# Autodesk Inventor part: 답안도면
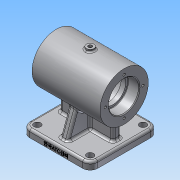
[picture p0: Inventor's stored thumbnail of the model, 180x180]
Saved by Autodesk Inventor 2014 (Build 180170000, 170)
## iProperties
Created: 2019-06
Part Number: 답안도면
Material: 알루미늄 6061
Document SubType Name: Modeling
Designer: NET
Density: 2.71 g/cm^3
Appearance: 알루미늄 - 평지
Mass: 642.889 g
Surface Area: 616.801 cm^2
Volume: 237.228 cm^3
Author: NET
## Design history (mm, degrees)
sketch "스케치1"
  geometry: L1 (45, 0)-(-45, 0); L2 (45, 0)-(45, 32); L3 (45, 32)-(-45, 32); L4 (-45, 32)-(-45, 0); L5 (45, 20)-(30.6, 20); L6 (30, 19.4)-(30, 17); L7 (30, 17)-(24, 17); L8 (24, 17)-(24, 22); L9 (21, 25)-(-21, 25); L10 (-24, 22)-(-24, 17); L11 (-24, 17)-(-30, 17); L12 (-30, 17)-(-30, 19.4); L13 (-30.6, 20)-(-45, 20); A1 r 3 centre (21, 22) between (24, 22) and (21, 25); A2 r 3 centre (-21, 22) between (-21, 25) and (-24, 22); A3 r 0.6 centre (30.6, 19.4) between (30.6, 20) and (30, 19.4); A4 r 0.6 centre (-30.6, 19.4) between (-30, 19.4) and (-30.6, 20); 7 further points
  constraints: 26 end point, 10 point on line, 8 point on circle, 8 tangent, 7 parallel, 5 perpendicular, 4 centre point, 2 equal radius, 2 midpoint, 1 coincident, 1 horizontal, 1 vertical alignment
  dimensions: "d0" = 90 distance of L1.start L1.end; "d1" = 64 diameter of L3 L1; "d2" = 40 diameter of L5 L1; "d3" = 34 diameter of L7 L1; "d4" = 50 diameter of L9 L1; "d5" = 40 diameter of L13 L1; "d6" = 34 diameter of L11 L1; "d7" = 48 distance of point (24, 25) point (-24, 25); "d8" = 15 distance of point (-30, 20) L13.end; "d9" = 15 distance of L5.start point (30, 20); "d10" = 3 radius of A1; "d11" = 0.6 radius of A3
revolve "회전1" sketch "스케치1" stored, may be unused: angle "d12" = 90 deg
chamfer "모따기1" distance "d13" = 1; stored, may be unused: second distance "d14" = 2, angle "d15" = 45 deg
sketch "스케치2"
  geometry: C1 r 32 at (0, 0) reference; 1 further point
  constraints: 1 vertical alignment
  dimensions: "d16" = 25 distance of C1.centre point (0, 25)
hole "구멍1" sketch "스케치2" at (0, 25) diameter "d17" = 3.242; stored, may be unused: countersink angle "d21" = 90 deg, drill point angle "d23" = 118 deg; dims "d18" = 7, "d19" = 4, "d20" = 2, "d22" = 9
node "작업 평면1"
sketch "스케치3"
  geometry: C1 r 5 at (0, 0); 1 further point
  constraints: 1 centre point, 1 coincident
  dimensions: "d28" = 10 diameter of C1
extrude "돌출1" join sketch "스케치3" stored distance "d29" = 10; taper "d30" = 0 deg
fillet "모깎기1" dims "d31" = 2
sketch "스케치4"
  geometry: C1 r 5 at (0, 0) reference
hole "구멍2" sketch "스케치4" at (0, 0) diameter "d32" = 4.917; stored, may be unused: countersink angle "d36" = 90 deg, drill point angle "d38" = 118 deg; dims "d33" = 7, "d34" = 4, "d35" = 2, "d37" = 20
node "작업 평면2"
sketch "스케치5"
  geometry: L1 (-45, -45)-(45, -45); L2 (45, -45)-(45, 45); L3 (45, 45)-(-45, 45); L4 (-45, 45)-(-45, -45); L5 (-45, -45)-(45, 45); L6 (45, -45)-(-45, 45); 1 further point
  constraints: 12 end point, 2 midpoint, 2 parallel, 1 horizontal, 1 perpendicular
  dimensions: "d40" = 90 distance of L2.end L3.end; "d41" = 90 distance of L1.end L2.end
extrude "돌출2" join sketch "스케치5" distance "d42" = 10; taper "d43" = 0 deg
fillet "모깎기2" dims "d44" = 10
fillet "모깎기3" dims "d45" = 3
sketch "스케치6"
  geometry: L1 (-35, -5)-(35, -5); L2 (35, -5)-(35, 5); L3 (35, 5)-(-35, 5); L4 (-35, 5)-(-35, -5); L5 (-35, -5)-(35, 5); L6 (35, -5)-(-35, 5); L7 (45, -35)-(45, 35) reference; 1 further point
  constraints: 12 end point, 2 midpoint, 2 parallel, 1 horizontal, 1 perpendicular
  dimensions: "d46" = 10 distance between parallel lines of L1 L3; "d47" = 10 distance between parallel lines of L7 L2
extrude "돌출3" join sketch "스케치6" stored distance "d48" = 10; taper "d49" = 0 deg
sketch "스케치7"
  geometry: L1 (45, -58)-(45, -65) reference; L2 (45, -65)-(-45, -65) reference; L3 (-45, -65)-(-45, -58) reference; L4 (-42, -55)-(-5, -55) reference; L5 (-5, -55)-(-5, -31.607) reference; L6 (-5, 33.272)-(-5, 35) reference; L7 (-5, 35)-(-2.458, 35) reference; L8 (-2.458, 35)-(-2.458, 24.879) reference; L9 (2.458, 24.879)-(2.458, 35) reference; L10 (2.458, 35)-(5, 35) reference; L11 (5, 35)-(5, 33.272) reference; L12 (5, -31.607)-(5, -55) reference; L13 (5, -55)-(42, -55) reference; L14 (-35, -55)-(-29.724, -40.505); A1 r 3 centre (42, -58) between (45, -58) and (42, -55) reference; A2 r 3 centre (-42, -58) between (-42, -55) and (-45, -58) reference; A3 r 32 centre (0, 0) between (-6.588, 31.314) and (-5, -31.607) reference; A4 r 25 centre (0, 0) between (-2.458, 24.879) and (2.458, 24.879) reference; A5 r 32 centre (0, 0) between (5, -31.607) and (6.588, 31.314) reference; 1 further point
  constraints: 2 end point, 1 point on line, 2 other
  dimensions: "d50" = 110 deg angle of L4 L14; "d51" = 10 distance from line of L3 L14.start
feature "리브1" sketch "스케치7" dims "d52" = 1, "d53" = 10, "d54" = 0, "d55" = 0, "d56" = 1, "d57" = 1
fillet "모깎기4" dims "d58" = 3
fillet "모깎기5" dims "d59" = 3
sketch "스케치8"
  geometry: A1 r 7 centre (35, -35) between (35, -42) and (42, -35) reference; A2 r 7 centre (35, 35) between (42, 35) and (35, 42) reference; A3 r 7 centre (-35, 35) between (-35, 42) and (-42, 35) reference; A4 r 7 centre (-35, -35) between (-42, -35) and (-35, -42) reference; 1 further point
hole "구멍3" sketch "스케치8" at (-35, -35), (35, -35), (35, 35), (-35, 35) diameter "d60" = 9; stored, may be unused: countersink angle "d64" = 90 deg, drill point angle "d66" = 118 deg; dims "d61" = 7, "d62" = 4, "d63" = 2, "d65" = 20
sketch "스케치9"
  geometry: L1 (0, 0)-(70, 0) reference; L2 (-10, 7)-(-10, 0) reference; 2 further points
  constraints: 1 other
  dimensions: "d67" = 4 distance from line of L1 point (35, 4); "d68" = 45 distance from line of L2 point (35, 4)
feature "엠보싱1" sketch "스케치9" dims "d0" = 90, "d1" = 64, "d2" = 40, "d3" = 34, "d4" = 50, "d5" = 40, "d6" = 34, "d7" = 48, "d8" = 15, "d9" = 15, "d10" = 3, "d11" = 0.6, "d69" = 0.5, "d70" = 0
sketch "스케치10"
  geometry: L1 (-22, -40)-(22, -40); L2 (40, -22)-(40, 22); L3 (22, 40)-(-22, 40); L4 (-40, 22)-(-40, -22); L5 (-40, -40)-(40, 40); L6 (40, -40)-(-40, 40); L7 (-25, -37)-(-25, -35); L8 (-37, -25)-(-35, -25); L9 (-37, 25)-(-35, 25); L10 (-25, 37)-(-25, 35); L11 (37, 25)-(35, 25); L12 (25, 37)-(25, 35); L13 (25, -37)-(25, -35); L14 (37, -25)-(35, -25); A1 r 10 centre (35, -35) between (35, -45) and (45, -35) reference; A2 r 10 centre (35, 35) between (45, 35) and (35, 45) reference; A3 r 10 centre (-35, 35) between (-35, 45) and (-45, 35) reference; A4 r 10 centre (-35, -35) between (-45, -35) and (-35, -45) reference; A5 r 10 centre (-35, 35) between (-25, 35) and (-35, 25); A6 r 10 centre (35, 35) between (35, 25) and (25, 35); A7 r 10 centre (35, -35) between (25, -35) and (35, -25); A8 r 10 centre (-35, -35) between (-35, -25) and (-25, -35); A9 r 3 centre (-22, -37) between (-25, -37) and (-22, -40); A10 r 3 centre (22, -37) between (22, -40) and (25, -37); A11 r 3 centre (37, -22) between (37, -25) and (40, -22); A12 r 3 centre (37, 22) between (40, 22) and (37, 25); A13 r 3 centre (22, 37) between (25, 37) and (22, 40); A14 r 3 centre (-22, 37) between (-22, 40) and (-25, 37); A15 r 3 centre (-37, 22) between (-37, 25) and (-40, 22); A16 r 3 centre (-37, -22) between (-40, -22) and (-37, -25); 2 further points
  constraints: 28 end point, 24 point on circle, 24 tangent, 12 centre point, 6 perpendicular, 5 equal radius, 4 coincident, 4 midpoint, 4 parallel, 1 horizontal
  dimensions: "d71" = 80 distance of L5.end L6.end; "d72" = 80 distance of L6.start L5.end; "d73" = 20 diameter of A5; "d74" = 20 diameter of A6; "d75" = 20 diameter of A7; "d76" = 20 diameter of A8; "d77" = 3 radius of A9; "d78" = 3 radius of A10; "d79" = 3 radius of A16
extrude "돌출4" cut sketch "스케치10" distance "d80" = 5; taper "d81" = 0 deg
node "솔리드1"
pattern_circular "원형 패턴1" dims angle "d25" = 360 deg
mirror "대칭1"
mirror "대칭2"
node "절단 모서리 투영1"
other parameters: "d27" = 35, "d39" = -65
